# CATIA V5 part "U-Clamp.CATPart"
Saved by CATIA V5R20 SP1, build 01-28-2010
Part number: U-Clamp
Bounding box of the stored display mesh (mm): x -22.987 to 22.987, y -6.35 to 6.35, z -25.4 to 28.702
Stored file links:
  D:\v5_r20\psrt_files_downloaded\c13-catia-v5r20-prt\c13-catia-v5r20-figr-13-43\Part & Asm files\U-Clamp.CATPart
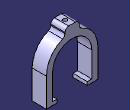
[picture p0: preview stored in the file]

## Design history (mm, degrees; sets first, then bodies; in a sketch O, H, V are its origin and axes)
Body1 (main body)
  Sketch1 on zx-plane, origin (0, 0, 0), H (-1, 0, 0), V (0, 0, 1)
    arc A1 centre (0, 0) radius 17.526 from (17.526, 0) to (-17.526, 0) ccw
    point P1 (-17.526, 0)
    point P2 (17.526, 0)
    line L1 (-17.526, 0) -> (-17.526, -22.352)
    point P3 (-17.526, -22.352)
    line L2 (-17.526, -22.352) -> (-13.462, -22.352)
    point P4 (-13.462, -22.352)
    line L3 (-13.462, -22.352) -> (-13.462, -25.4)
    point P5 (-13.462, -25.4)
    line L4 (-13.462, -25.4) -> (-22.987, -25.4)
    point P6 (-22.987, -25.4)
    line L5 (-22.987, -25.4) -> (-22.987, 0)
    point P7 (-22.987, 0)
    arc A2 centre (0, 0) radius 22.987 from (-22.987, 0) to (-6.35, 22.0925) cw
    point P9 (22.987, 0)
    point P10 (22.987, 0)
    point P11 (22.987, -25.4)
    line L6 (22.987, -25.4) -> (22.987, 0)
    point P12 (13.462, -25.4)
    line L7 (13.462, -25.4) -> (22.987, -25.4)
    point P13 (13.462, -22.352)
    line L8 (13.462, -22.352) -> (13.462, -25.4)
    point P14 (17.526, -22.352)
    line L9 (17.526, -22.352) -> (13.462, -22.352)
    point P15 (17.526, 0)
    line L10 (17.526, 0) -> (17.526, -22.352)
    line L11 (-6.35, 22.0925) -> (-6.35, 28.702)
    point P16 (-6.35, 28.702)
    line L12 (-6.35, 28.702) -> (6.35, 28.702)
    point P17 (6.35, 28.702)
    line L13 (6.35, 28.702) -> (6.35, 22.0925)
    point P18 (6.35, 22.0925)
    arc A3 centre (0, 0) radius 22.987 from (6.35, 22.0925) to (22.987, 0) cw
    radius A1 = 17.526
    distance L3 V = 13.462
    distance H L2 = 22.352
    distance H L4 = 25.4
    distance V L5 = 22.987
    distance P16 P17 = 12.7
    distance L11 V = 6.35
    distance L12 H = 28.702
    coincidence: P1 H, P2 H, P7 H, A2 P18, A2 A3, P2 P15, P9 P10
    tangency: L1 A1, A2 L5
    horizontal: L2 H, L4 H, L12 H
    vertical: L3 V, L5 V, L11 V, L13 V
    concentricity: A2 A1
    symmetry: P7 P10 V, P6 P11 V, L5 L6 V, P5 P12 V, L4 L7 V, P4 P13 V, L3 L8 V, P3 P14 V, L2 L9 V, P1 P15 V, L1 L10 V
  Pad1: profile Sketch1, direction (0, -1, 0), length 6.35, mirrored extent
  Fillet1: radius 3.302, on 4 edges
  Sketch2 on face of Pad1, origin (-0.057, 2.6412, 28.702), H (1, 0, 0), V (0, 1, 0)
    point P1 (0.057, -2.6412)
    reference intersected line E1 through (0.057, 0) direction (0, 1) from yz-plane
    reference intersected line E2 through (0, -2.6412) direction (-1, 0) from zx-plane
    coincidence: E1 P1, E2 P1
  Hole1: placed by Sketch2, at (0, 0, 28.702) direction (0, 0, -1), diameter 3.81, depth 25.4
